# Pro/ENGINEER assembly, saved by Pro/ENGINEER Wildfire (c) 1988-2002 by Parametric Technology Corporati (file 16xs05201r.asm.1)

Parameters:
  NB = "16XS05201R"
  NN = "16 - Series"
  NT = "Medium Heavy Duty Caster"
  NBSYN = "$PN.$CASTER."
  LINA = "16XS05201R"

Other parameters: PSOL_MULTISOLIDPART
